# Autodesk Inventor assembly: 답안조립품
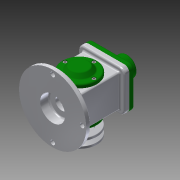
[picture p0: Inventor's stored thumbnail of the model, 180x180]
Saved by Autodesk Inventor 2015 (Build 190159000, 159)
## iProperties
Created: 2019-08
Part Number: 답안조립품
Document SubType Name: Assembly
Designer: a3
Author: a3
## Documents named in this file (18)
- C:\Users\a3\Desktop\490804V1007\답안조립품.iam
- C:\Users\a3\Desktop\490804V1007\본체.ipt
- C:\Users\a3\Desktop\490804V1007\덮개.ipt
- C:\Users\a3\Desktop\490804V1007\뒤커버.ipt
- C:\Users\a3\Desktop\490804V1007\앞커버.ipt
- C:\Users\a3\Desktop\490804V1007\베어링 17 x 40 x 12.ipt
- C:\Users\a3\Desktop\490804V1007\편심축.ipt
- C:\Users\a3\Desktop\490804V1007\링크.ipt
- C:\Users\a3\Desktop\490804V1007\슬라이더.ipt
- C:\Users\a3\Desktop\490804V1007\클레비스 핀 6 x 22.ipt
- 클레비스 핀 6 x 22.ipt
- C:\Users\a3\Desktop\490804V1007\E-링.ipt
- C:\Users\a3\Desktop\490804V1007\오일 실 17 30 8.ipt
- C:\Users\a3\Desktop\490804V1007\키 4 x 4 x 12.ipt
- C:\Users\a3\Desktop\490804V1007\V-벨트풀리.ipt
- C:\Users\a3\Desktop\490804V1007\와셔 4x16.ipt
- C:\Users\a3\Desktop\490804V1007\볼트 M4 x 10.ipt
- C:\Users\a3\Desktop\490804V1007\볼트 M4 x 8.ipt
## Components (2 placed, 2 different names)
1. E-링:1
2. V-벨트풀리:1 — 각도:1
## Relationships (1: Angle 1)
- 각도:1 [Angle]: V-벨트풀리:1
